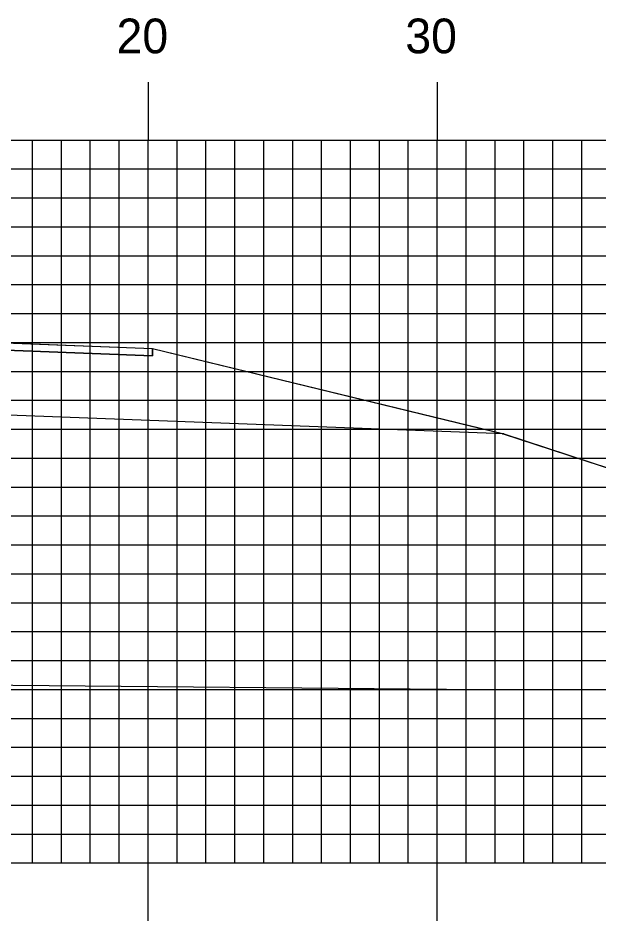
# Model space of a CAD drawing. Extents: x 1814915 to 1815259, y 442591 to 442811.
# Drawn here: x 1815096.52 to 1815116.62, y 442741.66 to 442772.88 of the extents above; entities that cross this region are included whole.
import ezdxf

# ---------------------------------------------------------------- set-up
doc = ezdxf.new("R2010")
doc.units = 0
for name, color, linetype in [('D_Drainage_Culvert', 7, 'Continuous'), ('D_Roadway_Centerline', 7, 'Continuous'), ('D_Roadway_Edge_Shoulder', 7, 'Continuous'), ('D_Roadway_SlopeLines', 7, 'Continuous'), ('D_Roadway_SubGrade', 7, 'Continuous'), ('H_V ANNOTATION', 7, 'Continuous'), ('MAJOR', 7, 'Continuous'), ('MINOR', 7, 'Continuous'), ('S_Roadway_Centerline', 7, 'Continuous')]:
    doc.layers.add(name, color=color, linetype=linetype)

msp = doc.modelspace()

# ---------------------------------------------------------------- linework, layer by layer
at = {"layer": 'D_Drainage_Culvert'}
for p, q in [((1815023.546, 442754.665), (1815135.546, 442754.665)), ((1815023.546, 442748.665), (1815135.546, 442748.665))]:
    msp.add_line(p, q, dxfattribs=at)
at = {"layer": 'D_Roadway_Centerline'}
msp.add_lwpolyline([(1815096.36, 442761.639), (1815101.177, 442761.455), (1815103.065, 442760.995), (1815104.293, 442760.697), (1815107.845, 442759.833), (1815112.167, 442758.781), (1815112.603, 442758.675), (1815113.272, 442758.512), (1815113.277, 442758.511), (1815113.323, 442758.5), (1815118.488, 442756.815), (1815119.981, 442756.329), (1815122.341, 442755.559)], dxfattribs=at)
at = {"layer": 'D_Roadway_Edge_Shoulder'}
msp.add_lwpolyline([(1815093.114, 442761.764), (1815101.177, 442761.455), (1815101.177, 442761.205), (1815093.114, 442761.514)], close=True, dxfattribs=at)
at = {"layer": 'D_Roadway_SlopeLines'}
msp.add_lwpolyline([(1815101.177, 442761.455), (1815113.272, 442758.512), (1815122.344, 442755.557)], dxfattribs=at)
at = {"layer": 'D_Roadway_SubGrade'}
msp.add_lwpolyline([(1815068.928, 442760.234), (1815049.915, 442759.798), (1815060.867, 442762.549), (1815060.867, 442762.299), (1815068.928, 442762.484), (1815081.021, 442761.992), (1815093.114, 442761.514), (1815101.177, 442761.205), (1815101.177, 442761.455), (1815113.323, 442758.5), (1815093.114, 442759.264), (1815081.021, 442759.742)], close=True, dxfattribs=at)
at = {"layer": 'MAJOR'}
for p, q in [((1815101.021, 442770.669), (1815101.021, 442768.665)), ((1815111.021, 442770.669), (1815111.021, 442768.665)), ((1814941.021, 442768.665), (1815221.021, 442768.665)), ((1814941.021, 442768.665), (1815221.021, 442768.665)), ((1815101.021, 442743.665), (1815101.021, 442768.665)), ((1815111.021, 442743.665), (1815111.021, 442768.665)), ((1814941.021, 442763.665), (1815221.021, 442763.665)), ((1814941.021, 442758.665), (1815221.021, 442758.665)), ((1814941.021, 442753.665), (1815221.021, 442753.665)), ((1814941.021, 442748.665), (1815221.021, 442748.665)), ((1814941.021, 442743.665), (1815221.021, 442743.665)), ((1814941.021, 442743.665), (1815221.021, 442743.665)), ((1815101.021, 442741.661), (1815101.021, 442743.665)), ((1815111.021, 442741.661), (1815111.021, 442743.665))]:
    msp.add_line(p, q, dxfattribs=at)
at = {"layer": 'MINOR'}
for p, q in [((1815097.021, 442743.665), (1815097.021, 442768.665)), ((1815098.021, 442743.665), (1815098.021, 442768.665)), ((1815099.021, 442743.665), (1815099.021, 442768.665)), ((1815100.021, 442743.665), (1815100.021, 442768.665)), ((1815102.021, 442743.665), (1815102.021, 442768.665)), ((1815103.021, 442743.665), (1815103.021, 442768.665)), ((1815104.021, 442743.665), (1815104.021, 442768.665)), ((1815105.021, 442743.665), (1815105.021, 442768.665)), ((1815106.021, 442743.665), (1815106.021, 442768.665)), ((1815107.021, 442743.665), (1815107.021, 442768.665)), ((1815108.021, 442743.665), (1815108.021, 442768.665)), ((1815109.021, 442743.665), (1815109.021, 442768.665)), ((1815110.021, 442743.665), (1815110.021, 442768.665)), ((1815112.021, 442743.665), (1815112.021, 442768.665)), ((1815113.021, 442743.665), (1815113.021, 442768.665)), ((1815114.021, 442743.665), (1815114.021, 442768.665)), ((1815115.021, 442743.665), (1815115.021, 442768.665)), ((1815116.021, 442743.665), (1815116.021, 442768.665)), ((1814941.021, 442767.665), (1815221.021, 442767.665)), ((1814941.021, 442766.665), (1815221.021, 442766.665)), ((1814941.021, 442765.665), (1815221.021, 442765.665)), ((1814941.021, 442764.665), (1815221.021, 442764.665)), ((1814941.021, 442762.665), (1815221.021, 442762.665)), ((1814941.021, 442761.665), (1815221.021, 442761.665)), ((1814941.021, 442760.665), (1815221.021, 442760.665)), ((1814941.021, 442759.665), (1815221.021, 442759.665)), ((1814941.021, 442757.665), (1815221.021, 442757.665)), ((1814941.021, 442756.665), (1815221.021, 442756.665)), ((1814941.021, 442755.665), (1815221.021, 442755.665)), ((1814941.021, 442754.665), (1815221.021, 442754.665)), ((1814941.021, 442752.665), (1815221.021, 442752.665)), ((1814941.021, 442751.665), (1815221.021, 442751.665)), ((1814941.021, 442750.665), (1815221.021, 442750.665)), ((1814941.021, 442749.665), (1815221.021, 442749.665)), ((1814941.021, 442747.665), (1815221.021, 442747.665)), ((1814941.021, 442746.665), (1815221.021, 442746.665)), ((1814941.021, 442745.665), (1815221.021, 442745.665)), ((1814941.021, 442744.665), (1815221.021, 442744.665))]:
    msp.add_line(p, q, dxfattribs=at)
at = {"layer": 'S_Roadway_Centerline'}
msp.add_lwpolyline([(1815005.992, 442749.908), (1815018.998, 442749.725), (1815021.668, 442749.599), (1815038.193, 442749.577), (1815038.357, 442749.576), (1815038.485, 442749.576), (1815040.318, 442749.591), (1815054.077, 442749.699), (1815055.256, 442749.702), (1815070.887, 442749.599), (1815083.088, 442749.849), (1815088.074, 442749.897), (1815095.082, 442749.831), (1815112.583, 442749.662), (1815120.304, 442749.652), (1815126.402, 442749.71), (1815137.574, 442749.683)], dxfattribs=at)

# ---------------------------------------------------------------- texts
at = {"layer": 'H_V ANNOTATION'}
for s, p in [('20', (1815099.929, 442771.665)), ('30', (1815109.918, 442771.665))]:
    msp.add_text(s, height=1.2, dxfattribs=at).set_placement(p)

doc.saveas('drawing.dxf')
